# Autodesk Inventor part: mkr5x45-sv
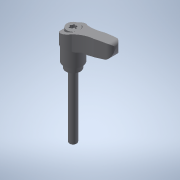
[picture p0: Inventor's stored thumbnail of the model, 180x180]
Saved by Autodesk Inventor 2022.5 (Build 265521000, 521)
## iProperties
Created: 2017-09
Part Number: mkr5x45-sv
Material: 一般
Document SubType Name: Modeling
Designer: imaocorp
Density: 1 g/cm^3
Appearance: 既定
Author: imaocorp
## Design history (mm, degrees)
node "mkr5x45-sv.x_t1"
node "mkr5x45-sv"
node "Base1"
